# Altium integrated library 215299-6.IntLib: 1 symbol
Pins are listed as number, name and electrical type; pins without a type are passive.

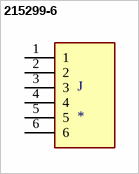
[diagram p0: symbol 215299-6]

## 215299-6
designator J
MF: {'manufacturer': 'TE Connectivity'}; MP: 215299-6
footprint TE_215299-6
pins: 1, 2, 3, 4, 5, 6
